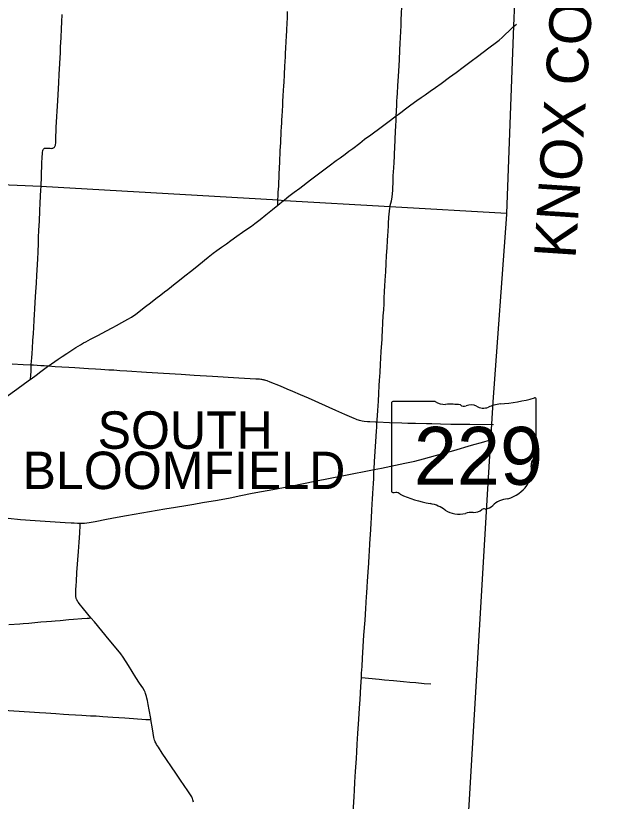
# Model space of a CAD drawing. Extents: x 1815539 to 1947826, y 273303 to 993194.
# Drawn here: x 1917520 to 1931591, y 866502 to 885394 of the extents above; entities that cross this region are included whole.
import ezdxf

# ---------------------------------------------------------------- set-up
doc = ezdxf.new("R2010")
doc.units = 0
for name, color, linetype in [('GM_X_Adjacent_County_Text', 7, 'Continuous'), ('GM_X_County', 7, 'Continuous'), ('GM_X_County_Road', 7, 'Continuous'), ('GM_X_State_Route', 7, 'Continuous'), ('GM_X_Township', 7, 'Continuous'), ('GM_X_Township_Road', 7, 'Continuous'), ('GM_X_Township_Text', 7, 'Continuous'), ('SC_Shading3', 7, 'Continuous')]:
    doc.layers.add(name, color=color, linetype=linetype)

msp = doc.modelspace()

# ---------------------------------------------------------------- linework, layer by layer
at = {"layer": 'GM_X_County'}
msp.add_lwpolyline([(1929509, 885709), (1929483, 885147), (1929313, 880637), (1929312, 880613), (1928987, 876105), (1928954, 875572), (1928932, 875213), (1928849, 873883), (1928341, 865325), (1928314, 865105), (1928189, 862861), (1927988, 859624), (1927907, 858279), (1927777, 856135), (1927658, 854184), (1924873, 854361), (1922111, 854537), (1916549, 854893), (1915609, 854967), (1909640, 855342), (1905546, 855583), (1900992, 855867)], dxfattribs=at)
at = {"layer": 'GM_X_County_Road'}
for points in [[(1926681, 883336), (1926686, 883438), (1926691, 883519), (1926703, 883715), (1926716, 883928), (1926732, 884197), (1926739, 884331), (1926751, 884567), (1926761, 884730), (1926769, 884861), (1926777, 885025), (1926781, 885151), (1926786, 885287), (1926792, 885451), (1926798, 885599), (1926802, 885697), (1926807, 885779), (1926811, 885855), (1926812, 885867)], [(1926666, 882988), (1926707, 883019), (1926773, 883068), (1926888, 883156), (1926983, 883225), (1927102, 883312), (1927155, 883351), (1927261, 883427), (1927356, 883492), (1927477, 883576), (1927611, 883670), (1927745, 883766), (1927942, 883913), (1928101, 884029), (1928272, 884157), (1928468, 884304), (1928613, 884412), (1928888, 884619), (1929072, 884757), (1929136, 884809), (1929211, 884873), (1929259, 884917), (1929400, 885055), (1929471, 885123), (1929555, 885194)], [(1926666, 882988), (1926670, 883094), (1926678, 883258), (1926681, 883336)], [(1923954, 880947), (1923981, 880969), (1924084, 881050), (1924214, 881150), (1924345, 881249), (1924607, 881446), (1925053, 881780), (1925224, 881909), (1925316, 881977), (1925434, 882065), (1925526, 882133), (1925618, 882202), (1925787, 882332), (1925905, 882421), (1926050, 882529), (1926300, 882714), (1926458, 882832), (1926666, 882988)], [(1926627, 882187), (1926631, 882276), (1926636, 882358), (1926640, 882440), (1926655, 882751), (1926661, 882865), (1926666, 882979), (1926666, 882988)], [(1926515, 880801), (1926521, 880827), (1926536, 880888), (1926549, 880942), (1926558, 880985), (1926566, 881037), (1926574, 881110), (1926579, 881199), (1926588, 881429), (1926593, 881545), (1926603, 881736), (1926610, 881867), (1926618, 882015), (1926623, 882113), (1926627, 882187)], [(1923818, 880838), (1923954, 880947)], [(1918304, 876971), (1918377, 877023), (1918541, 877132), (1918636, 877196), (1918745, 877270), (1918868, 877350), (1918965, 877411), (1919076, 877481), (1919146, 877523), (1919204, 877554), (1919320, 877615), (1919378, 877645), (1919480, 877698), (1919611, 877765), (1919684, 877804), (1919857, 877898), (1919943, 877945), (1920072, 878017), (1920215, 878096), (1920300, 878146), (1920356, 878182), (1920396, 878210), (1920448, 878250), (1920641, 878401), (1920758, 878492), (1920888, 878591), (1921005, 878681), (1921096, 878751), (1921174, 878812), (1921354, 878953), (1921418, 879004), (1921546, 879106), (1921789, 879301), (1921917, 879405), (1922147, 879589), (1922262, 879681), (1922354, 879750), (1922461, 879826), (1922581, 879911), (1922688, 879987), (1922836, 880090), (1922970, 880185), (1923077, 880260), (1923185, 880336), (1923264, 880395), (1923393, 880496), (1923533, 880609), (1923687, 880732), (1923818, 880838)], [(1926202, 875626), (1926204, 875668), (1926219, 875897), (1926234, 876127), (1926245, 876307), (1926257, 876503), (1926264, 876618), (1926275, 876814), (1926287, 877011), (1926296, 877158), (1926305, 877322), (1926322, 877617), (1926325, 877682), (1926332, 877813), (1926343, 878010), (1926352, 878174), (1926362, 878321), (1926370, 878468), (1926373, 878534), (1926376, 878599), (1926385, 878763), (1926391, 878894), (1926398, 879025), (1926405, 879140), (1926410, 879238), (1926421, 879434), (1926432, 879631), (1926444, 879810), (1926456, 879990), (1926462, 880105), (1926468, 880203), (1926475, 880351), (1926478, 880400), (1926486, 880547), (1926498, 880690), (1926507, 880763), (1926515, 880801)], [(1917877, 876650), (1917891, 876661), (1918009, 876749), (1918126, 876839), (1918284, 876956), (1918304, 876971)], [(1918304, 876971), (1918468, 876957), (1918631, 876947), (1918795, 876938), (1918942, 876930), (1919269, 876912), (1919433, 876901), (1919564, 876892), (1919760, 876880), (1919875, 876874), (1920022, 876864), (1920186, 876854), (1920660, 876823), (1921068, 876797), (1921493, 876773), (1921805, 876753), (1922247, 876726), (1922884, 876687), (1923293, 876663), (1923353, 876660), (1923377, 876658), (1923408, 876653), (1923428, 876650), (1923451, 876647), (1923464, 876644), (1923482, 876640), (1923501, 876635), (1923522, 876629), (1923554, 876619), (1923628, 876592), (1923871, 876492), (1924037, 876423), (1924173, 876367), (1924354, 876288), (1924549, 876201), (1925207, 875906), (1925417, 875812), (1925642, 875712), (1925681, 875696), (1925719, 875683), (1925749, 875674), (1925775, 875667), (1925809, 875660), (1925846, 875653), (1925897, 875647), (1925977, 875639), (1926031, 875634), (1926169, 875628), (1926202, 875626)], [(1917291, 876232), (1917545, 876411), (1917732, 876545), (1917877, 876650)], [(1926131, 874480), (1926131, 874490), (1926142, 874670), (1926181, 875276), (1926189, 875407), (1926194, 875489), (1926200, 875603), (1926202, 875626)], [(1926202, 875626), (1926501, 875612), (1926796, 875602), (1926944, 875599), (1927124, 875594), (1927387, 875587), (1927518, 875584), (1927731, 875579), (1927976, 875573), (1928436, 875567), (1928999, 875559)], [(1925827, 869476), (1925832, 869582), (1925842, 869746), (1925854, 869943), (1925889, 870499), (1925914, 870859), (1925932, 871135), (1925951, 871429), (1925956, 871510), (1925965, 871658), (1925974, 871788), (1925990, 872018), (1926005, 872230), (1926015, 872411), (1926021, 872509), (1926032, 872705), (1926051, 873033), (1926062, 873196), (1926069, 873311), (1926081, 873507), (1926089, 873638), (1926097, 873786), (1926103, 873884), (1926111, 874047), (1926115, 874129), (1926123, 874277), (1926129, 874424), (1926131, 874480)], [(1925577, 865482), (1925590, 865650), (1925613, 866026), (1925635, 866353), (1925651, 866614), (1925660, 866761), (1925672, 866958), (1925687, 867219), (1925706, 867530), (1925716, 867693), (1925727, 867873), (1925743, 868135), (1925765, 868478), (1925780, 868739), (1925793, 868952), (1925813, 869262), (1925827, 869476)]]:
    msp.add_lwpolyline(points, dxfattribs=at)
at = {"layer": 'GM_X_State_Route'}
msp.add_lwpolyline([(1917338, 873308), (1917632, 873282), (1917990, 873255), (1918465, 873224), (1918710, 873208), (1918852, 873199), (1918922, 873195), (1919001, 873192), (1919070, 873191), (1919121, 873193), (1919172, 873194), (1919226, 873199), (1919282, 873205), (1919428, 873229), (1919698, 873284), (1919956, 873334), (1920182, 873374), (1921104, 873533), (1921362, 873577), (1921605, 873617), (1921799, 873650), (1922009, 873687), (1922365, 873747), (1922671, 873803), (1922928, 873856), (1923202, 873911), (1923783, 874016), (1924201, 874098), (1924393, 874136), (1924750, 874207), (1925038, 874265), (1925408, 874339), (1926131, 874480), (1926311, 874516), (1926872, 874630), (1927112, 874685), (1927319, 874736), (1927604, 874814), (1928045, 874940), (1928471, 875062), (1928769, 875150), (1928977, 875210)], dxfattribs=at)
at = {"layer": 'GM_X_Township'}
msp.add_lwpolyline([(1929313, 880637), (1926519, 880798), (1923978, 880945), (1923826, 880954), (1918127, 881283), (1915079, 881414), (1912418, 881561), (1907482, 881867), (1902065, 882212), (1902276, 885593), (1902366, 887154), (1902378, 887248), (1902624, 890798), (1902935, 895772), (1903241, 901246), (1903453, 905734), (1903500, 906547), (1903661, 909327)], dxfattribs=at)
at = {"layer": 'GM_X_Township_Road'}
for points in [[(1923820, 880956), (1923824, 881070), (1923829, 881152), (1923839, 881298), (1923853, 881591), (1923866, 881870), (1923878, 882148), (1923888, 882345), (1923900, 882607), (1923908, 882722), (1923913, 882813), (1923918, 882885), (1923924, 882983), (1923931, 883098), (1923937, 883245), (1923941, 883326), (1923949, 883474), (1923956, 883588), (1923964, 883719), (1923969, 883784), (1923979, 883980), (1923989, 884177), (1924003, 884406), (1924006, 884503), (1924011, 884602), (1924021, 884782), (1924026, 884896), (1924033, 885044), (1924043, 885223), (1924048, 885335), (1924050, 885494)], [(1918129, 881284), (1918138, 881538), (1918150, 881845), (1918157, 881990), (1918163, 882083), (1918166, 882116), (1918170, 882141), (1918175, 882157), (1918181, 882172), (1918189, 882186), (1918201, 882198), (1918215, 882205), (1918231, 882209), (1918247, 882211), (1918264, 882212), (1918280, 882211), (1918346, 882206), (1918379, 882204), (1918395, 882205), (1918411, 882209), (1918426, 882215), (1918440, 882223), (1918452, 882235), (1918462, 882248), (1918469, 882262), (1918474, 882278), (1918478, 882294), (1918481, 882327), (1918484, 882409), (1918495, 882704), (1918508, 882966), (1918516, 883097), (1918531, 883343), (1918557, 883785), (1918566, 883982), (1918593, 884506), (1918599, 884638), (1918611, 884867), (1918622, 885080), (1918630, 885247), (1918638, 885424)], [(1917894, 876997), (1917901, 877093), (1917905, 877158), (1917914, 877281), (1917922, 877392), (1917933, 877584), (1917943, 877748), (1917952, 877895), (1917961, 878075), (1917968, 878207), (1917976, 878338), (1917988, 878501), (1918002, 878754), (1918015, 878960), (1918028, 879157), (1918040, 879403), (1918047, 879551), (1918055, 879698), (1918064, 879928), (1918070, 880059), (1918079, 880240), (1918089, 880453), (1918101, 880699), (1918110, 880896), (1918126, 881207), (1918129, 881284)], [(1923818, 880838), (1923819, 880884), (1923819, 880941), (1923820, 880956)], [(1917437, 877022), (1917699, 877009), (1917894, 876997)], [(1917877, 876650), (1917878, 876686), (1917880, 876719), (1917888, 876867), (1917893, 876955), (1917894, 876994), (1917894, 876997)], [(1917894, 876997), (1917944, 876994), (1918125, 876982), (1918202, 876978), (1918264, 876974), (1918304, 876971)], [(1919327, 870913), (1919147, 871128), (1919046, 871257), (1919026, 871285), (1919015, 871300), (1919002, 871320), (1918997, 871329), (1918992, 871339), (1918986, 871351), (1918982, 871363), (1918976, 871380), (1918971, 871395), (1918968, 871410), (1918966, 871419), (1918965, 871428), (1918964, 871436), (1918963, 871446), (1918963, 871459), (1918964, 871479), (1918964, 871499), (1918965, 871534), (1918968, 871587), (1918973, 871693), (1918979, 871786), (1918992, 872001), (1919027, 872508), (1919042, 872736), (1919057, 872949), (1919069, 873145), (1919070, 873191)], [(1917357, 870750), (1917619, 870770), (1917701, 870776), (1917831, 870788), (1917978, 870802), (1918126, 870815), (1918257, 870825), (1918381, 870835), (1918469, 870843), (1918584, 870853), (1918797, 870872), (1918911, 870880), (1919108, 870895), (1919239, 870904), (1919288, 870909), (1919327, 870913)], [(1920770, 868466), (1920766, 868489), (1920727, 868698), (1920702, 868827), (1920684, 868924), (1920672, 868980), (1920663, 869022), (1920657, 869046), (1920650, 869073), (1920642, 869097), (1920630, 869123), (1920612, 869159), (1920571, 869230), (1920498, 869339), (1920410, 869477), (1920230, 869771), (1920105, 869964), (1920048, 870044), (1919975, 870133), (1919764, 870383), (1919410, 870814), (1919327, 870913)], [(1925827, 869476), (1926253, 869438), (1926384, 869426), (1926597, 869408), (1926842, 869385), (1926990, 869370), (1927137, 869356), (1927333, 869338), (1927497, 869323)], [(1916718, 868726), (1917848, 868654), (1918093, 868639), (1918240, 868628), (1918485, 868612), (1918665, 868599), (1918796, 868591), (1918960, 868581), (1919107, 868571), (1919320, 868559), (1919451, 868553), (1919614, 868543), (1919855, 868526), (1920138, 868506), (1920350, 868491), (1920645, 868472), (1920747, 868467), (1920770, 868466)], [(1921792, 866478), (1921774, 866538), (1921765, 866565), (1921757, 866587), (1921749, 866608), (1921734, 866637), (1921720, 866661), (1921706, 866683), (1921656, 866757), (1921478, 867013), (1921367, 867175), (1921039, 867662), (1920947, 867803), (1920905, 867871), (1920886, 867906), (1920874, 867929), (1920865, 867952), (1920858, 867972), (1920848, 868005), (1920842, 868037), (1920807, 868247), (1920770, 868466)]]:
    msp.add_lwpolyline(points, dxfattribs=at)
at = {"layer": 'SC_Shading3'}
for p, q in [((1926547, 876077), (1926547, 873964)), ((1927601, 876114), (1926581, 876114)), ((1930027, 875061), (1930027, 876166)), ((1930027, 875061), (1930027, 875061))]:
    msp.add_line(p, q, dxfattribs=at)
for centre, major_axis, start_param, end_param in [((1928788, 878995), (3691, 0), 4.814394, 5.042369), ((1929989, 876171), (38.7, 0), 6.141152, 7.989035), ((1926587, 876082), (40.3, 0), 1.712693, 3.28349), ((1927843, 876359), (391, 0), 4.042523, 4.731795), ((1927973, 874927), (1404, 0), 1.404758, 1.657858), ((1928292, 876093), (113, 0), 3.836095, 5.185415), ((1928457, 875848), (235, 0), 0.950623, 2.079405), ((1929258, 875468), (743, 0), 1.699011, 2.107814), ((1928760, 876183), (282, 0), 4.081561, 5.145723), ((1930018, 874979), (60, 0), 1.883978, 3.671073), ((1929637, 874840), (360, 0), 5.934695, 6.695948), ((1929986, 875056), (41.5, 0), 5.05454, 6.418171), ((1930166, 874598), (262, 0), 2.387724, 3.262537), ((1928994, 874457), (923, 0), 5.101752, 6.440018), ((1926587, 873959), (40.7, 0), 3.00124, 4.508301), ((1926657, 873842), (112, 0), 0.519207, 1.627899), ((1926593, 874176), (310, 0), 4.665946, 4.897461), ((1928070, 875741), (2665, 0), 4.195997, 4.488961), ((1929384, 873371), (506, 0), 1.647645, 2.488434), ((1927276, 873015), (834, 0), 0.823519, 1.323587), ((1928743, 873759), (298, 0), 4.937069, 5.64225), ((1928177, 873832), (529, 0), 4.026481, 4.996735), ((1928483, 873101), (435, 0), 1.495662, 1.94098), ((1928522, 873673), (282, 0), 4.691044, 5.507374), ((1928777, 873469), (79.4, 0), 1.147584, 2.315152)]:
    msp.add_ellipse(centre, major_axis=major_axis, ratio=0.8, start_param=start_param, end_param=end_param, dxfattribs=at)

# ---------------------------------------------------------------- texts
at = {"layer": 'GM_X_Adjacent_County_Text'}
msp.add_text('KNOX COUNTY', height=1000, rotation=86.2231, dxfattribs=at).set_placement((1930970, 879537))
at = {"layer": 'GM_X_Township_Text'}
for s, p in [('SOUTH', (1919487, 874979)), ('BLOOMFIELD', (1917683, 874010))]:
    msp.add_text(s, height=900, rotation=0, dxfattribs=at).set_placement(p)
at = {"layer": 'SC_Shading3'}
msp.add_text('229', height=1392.2, dxfattribs=at).set_placement((1927087, 874113))

doc.saveas('drawing.dxf')
